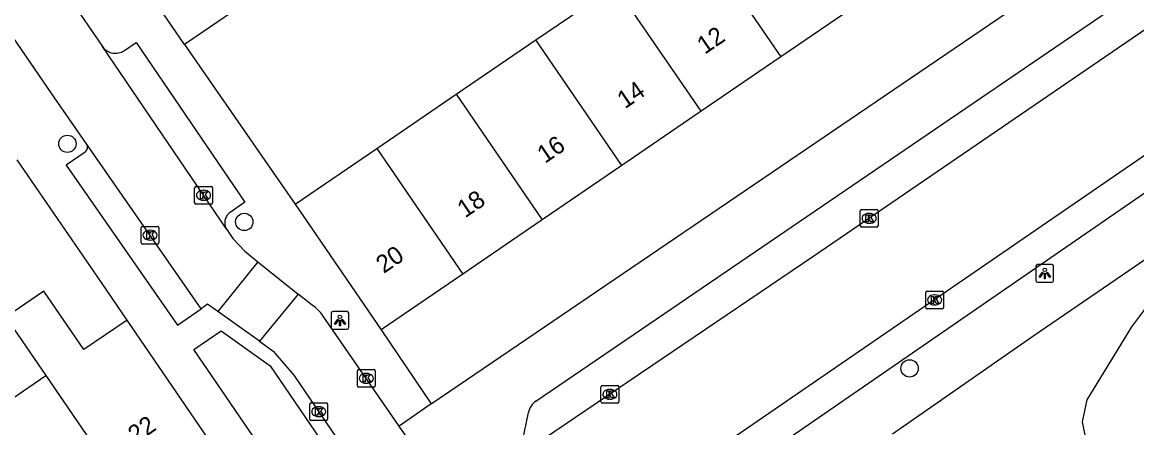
# Model space of a CAD drawing. Extents: x 157466 to 158888, y 383063 to 384677.
# Drawn here: x 158262.6 to 158325.5, y 383755.9 to 383778.8 of the extents above; entities that cross this region are included whole.
import ezdxf

# ---------------------------------------------------------------- set-up
doc = ezdxf.new("R2010")
doc.units = 0
for name, color, linetype in [('IMGEO_Boom', 7, 'Continuous'), ('IMGEO_Groenvoorziening', 7, 'Continuous'), ('IMGEO_Kolk', 7, 'Continuous'), ('IMGEO_Lichtpunt', 7, 'Continuous'), ('IMGEO_Muur', 7, 'Continuous'), ('IMGEO_Pand', 7, 'Continuous'), ('IMGEO_Pand_nummerreeks', 7, 'Continuous'), ('IMGEO_Rijbaan_lokaal_open', 7, 'Continuous'), ('IMGEO_Voetpad_open', 7, 'Continuous')]:
    doc.layers.add(name, color=color, linetype=linetype)

msp = doc.modelspace()

# ---------------------------------------------------------------- linework, layer by layer
at = {"layer": 'IMGEO_Boom'}
for centre in [(158265.189, 383771.9), (158275.165, 383767.49), (158312.693, 383759.216)]:
    msp.add_circle(centre, 0.489, dxfattribs=at)
at = {"layer": 'IMGEO_Groenvoorziening'}
msp.add_lwpolyline([(158334.12, 383750.607), (158332.791, 383751.81), (158334.867, 383754.492), (158334.342, 383755.707), (158335.525, 383757.421), (158335.831, 383758.461), (158335.729, 383760.44), (158335.26, 383762.521), (158334.199, 383764.378), (158332.852, 383765.317), (158331.363, 383765.643), (158329.241, 383765.255), (158327.956, 383764.603), (158326.446, 383763.215), (158325.206, 383761.562), (158322.692, 383757.441), (158322.427, 383756.197), (158322.692, 383754.891), (158323.059, 383754.054), (158339.545, 383730.388)], dxfattribs=at)
at = {"layer": 'IMGEO_Kolk'}
for p, q in [((158272.367, 383768.57), (158272.367, 383769.422)), ((158272.442, 383769.496), (158273.294, 383769.496)), ((158272.855, 383769.276), (158272.88, 383769.276)), ((158273.368, 383769.422), (158273.368, 383768.57)), ((158273.294, 383768.496), (158272.442, 383768.496)), ((158272.878, 383768.716), (158272.853, 383768.716)), ((158309.91, 383767.263), (158309.91, 383768.115)), ((158309.985, 383768.189), (158310.837, 383768.189)), ((158310.398, 383767.969), (158310.423, 383767.969)), ((158310.911, 383768.115), (158310.911, 383767.263)), ((158269.353, 383766.313), (158269.353, 383767.165)), ((158269.428, 383767.239), (158270.28, 383767.239)), ((158270.354, 383767.165), (158270.354, 383766.313)), ((158310.837, 383767.189), (158309.985, 383767.189)), ((158310.421, 383767.409), (158310.396, 383767.409)), ((158269.841, 383767.019), (158269.866, 383767.019)), ((158270.28, 383766.239), (158269.428, 383766.239)), ((158269.864, 383766.459), (158269.839, 383766.459)), ((158313.601, 383762.657), (158313.601, 383763.509)), ((158313.676, 383763.583), (158314.528, 383763.583)), ((158314.602, 383763.509), (158314.602, 383762.657)), ((158314.112, 383762.803), (158314.087, 383762.803)), ((158314.089, 383763.363), (158314.114, 383763.363)), ((158314.528, 383762.583), (158313.676, 383762.583)), ((158281.545, 383758.226), (158281.545, 383759.078)), ((158281.62, 383759.152), (158282.472, 383759.152)), ((158282.546, 383759.078), (158282.546, 383758.226)), ((158282.056, 383758.372), (158282.031, 383758.372)), ((158282.033, 383758.932), (158282.058, 383758.932)), ((158282.472, 383758.152), (158281.62, 383758.152)), ((158295.286, 383757.326), (158295.286, 383758.178)), ((158295.361, 383758.252), (158296.213, 383758.252)), ((158295.774, 383758.032), (158295.799, 383758.032)), ((158296.287, 383758.178), (158296.287, 383757.326)), ((158278.867, 383756.347), (158278.867, 383757.199)), ((158278.942, 383757.273), (158279.794, 383757.273)), ((158279.868, 383757.199), (158279.868, 383756.347)), ((158296.213, 383757.252), (158295.361, 383757.252)), ((158295.797, 383757.472), (158295.772, 383757.472)), ((158279.378, 383756.493), (158279.353, 383756.493)), ((158279.355, 383757.053), (158279.38, 383757.053)), ((158279.794, 383756.273), (158278.942, 383756.273))]:
    msp.add_line(p, q, dxfattribs=at)
for points in [[(158272.367, 383768.57), (158272.367, 383769.422)], [(158272.442, 383769.496), (158273.294, 383769.496)], [(158272.688, 383769.196), (158272.811, 383769.196), (158272.811, 383769.045), (158272.941, 383769.196), (158273.105, 383769.196), (158272.959, 383769.045), (158273.112, 383768.796), (158272.96, 383768.796), (158272.875, 383768.96), (158272.811, 383768.893), (158272.811, 383768.796), (158272.688, 383768.796), (158272.688, 383769.196)], [(158273.368, 383769.422), (158273.368, 383768.57)], [(158273.294, 383768.496), (158272.442, 383768.496)], [(158309.91, 383767.263), (158309.91, 383768.115)], [(158309.985, 383768.189), (158310.837, 383768.189)], [(158310.231, 383767.889), (158310.354, 383767.889), (158310.354, 383767.738), (158310.484, 383767.889), (158310.648, 383767.889), (158310.502, 383767.738), (158310.655, 383767.489), (158310.503, 383767.489), (158310.418, 383767.653), (158310.354, 383767.586), (158310.354, 383767.489), (158310.231, 383767.489), (158310.231, 383767.889)], [(158310.911, 383768.115), (158310.911, 383767.263)], [(158269.353, 383766.313), (158269.353, 383767.165)], [(158269.428, 383767.239), (158270.28, 383767.239)], [(158270.354, 383767.165), (158270.354, 383766.313)], [(158310.837, 383767.189), (158309.985, 383767.189)], [(158269.674, 383766.939), (158269.797, 383766.939), (158269.797, 383766.788), (158269.927, 383766.939), (158270.091, 383766.939), (158269.945, 383766.788), (158270.098, 383766.539), (158269.946, 383766.539), (158269.861, 383766.703), (158269.797, 383766.636), (158269.797, 383766.539), (158269.674, 383766.539), (158269.674, 383766.939)], [(158270.28, 383766.239), (158269.428, 383766.239)], [(158313.601, 383762.657), (158313.601, 383763.509)], [(158313.676, 383763.583), (158314.528, 383763.583)], [(158314.602, 383763.509), (158314.602, 383762.657)], [(158313.922, 383763.283), (158314.045, 383763.283), (158314.045, 383763.132), (158314.175, 383763.283), (158314.339, 383763.283), (158314.193, 383763.132), (158314.346, 383762.883), (158314.194, 383762.883), (158314.109, 383763.047), (158314.045, 383762.98), (158314.045, 383762.883), (158313.922, 383762.883), (158313.922, 383763.283)], [(158314.528, 383762.583), (158313.676, 383762.583)], [(158281.545, 383758.226), (158281.545, 383759.078)], [(158281.62, 383759.152), (158282.472, 383759.152)], [(158282.546, 383759.078), (158282.546, 383758.226)], [(158281.866, 383758.852), (158281.989, 383758.852), (158281.989, 383758.701), (158282.119, 383758.852), (158282.283, 383758.852), (158282.137, 383758.701), (158282.29, 383758.452), (158282.138, 383758.452), (158282.053, 383758.616), (158281.989, 383758.549), (158281.989, 383758.452), (158281.866, 383758.452), (158281.866, 383758.852)], [(158282.472, 383758.152), (158281.62, 383758.152)], [(158295.286, 383757.326), (158295.286, 383758.178)], [(158295.361, 383758.252), (158296.213, 383758.252)], [(158295.607, 383757.952), (158295.73, 383757.952), (158295.73, 383757.801), (158295.86, 383757.952), (158296.024, 383757.952), (158295.878, 383757.801), (158296.031, 383757.552), (158295.879, 383757.552), (158295.794, 383757.716), (158295.73, 383757.649), (158295.73, 383757.552), (158295.607, 383757.552), (158295.607, 383757.952)], [(158296.287, 383758.178), (158296.287, 383757.326)], [(158278.867, 383756.347), (158278.867, 383757.199)], [(158278.942, 383757.273), (158279.794, 383757.273)], [(158279.868, 383757.199), (158279.868, 383756.347)], [(158296.213, 383757.252), (158295.361, 383757.252)], [(158279.188, 383756.973), (158279.311, 383756.973), (158279.311, 383756.822), (158279.441, 383756.973), (158279.605, 383756.973), (158279.459, 383756.822), (158279.612, 383756.573), (158279.46, 383756.573), (158279.375, 383756.737), (158279.311, 383756.67), (158279.311, 383756.573), (158279.188, 383756.573), (158279.188, 383756.973)], [(158279.794, 383756.273), (158278.942, 383756.273)]]:
    msp.add_lwpolyline(points, dxfattribs=at)
for centre, start, end in [((158272.444, 383769.42), 91.55205, 178.44795), ((158272.444, 383769.42), 91.55205, 178.44795), ((158273.292, 383769.42), 1.55205, 88.44795), ((158273.292, 383769.42), 1.55205, 88.44795), ((158272.444, 383768.572), 181.55205, 268.44795), ((158272.444, 383768.572), 181.55205, 268.44795), ((158273.292, 383768.572), 271.55205, 358.44795), ((158273.292, 383768.572), 271.55205, 358.44795), ((158309.987, 383768.113), 91.55205, 178.44795), ((158309.987, 383768.113), 91.55205, 178.44795), ((158310.835, 383768.113), 1.55205, 88.44795), ((158310.835, 383768.113), 1.55205, 88.44795), ((158269.43, 383767.163), 91.55205, 178.44795), ((158269.43, 383767.163), 91.55205, 178.44795), ((158270.278, 383767.163), 1.55205, 88.44795), ((158270.278, 383767.163), 1.55205, 88.44795), ((158309.987, 383767.265), 181.55205, 268.44795), ((158309.987, 383767.265), 181.55205, 268.44795), ((158310.835, 383767.265), 271.55205, 358.44795), ((158310.835, 383767.265), 271.55205, 358.44795), ((158269.43, 383766.315), 181.55205, 268.44795), ((158269.43, 383766.315), 181.55205, 268.44795), ((158270.278, 383766.315), 271.55205, 358.44795), ((158270.278, 383766.315), 271.55205, 358.44795), ((158313.678, 383763.507), 91.55205, 178.44795), ((158313.678, 383763.507), 91.55205, 178.44795), ((158314.526, 383763.507), 1.55205, 88.44795), ((158314.526, 383763.507), 1.55205, 88.44795), ((158313.678, 383762.659), 181.55205, 268.44795), ((158313.678, 383762.659), 181.55205, 268.44795), ((158314.526, 383762.659), 271.55205, 358.44795), ((158314.526, 383762.659), 271.55205, 358.44795), ((158281.622, 383759.076), 91.55205, 178.44795), ((158281.622, 383759.076), 91.55205, 178.44795), ((158282.47, 383759.076), 1.55205, 88.44795), ((158282.47, 383759.076), 1.55205, 88.44795), ((158281.622, 383758.228), 181.55205, 268.44795), ((158281.622, 383758.228), 181.55205, 268.44795), ((158282.47, 383758.228), 271.55205, 358.44795), ((158282.47, 383758.228), 271.55205, 358.44795), ((158295.363, 383758.176), 91.55205, 178.44795), ((158295.363, 383758.176), 91.55205, 178.44795), ((158296.211, 383758.176), 1.55205, 88.44795), ((158296.211, 383758.176), 1.55205, 88.44795), ((158278.944, 383757.197), 91.55205, 178.44795), ((158278.944, 383757.197), 91.55205, 178.44795), ((158279.792, 383757.197), 1.55205, 88.44795), ((158279.792, 383757.197), 1.55205, 88.44795), ((158295.363, 383757.328), 181.55205, 268.44795), ((158295.363, 383757.328), 181.55205, 268.44795), ((158296.211, 383757.328), 271.55205, 358.44795), ((158296.211, 383757.328), 271.55205, 358.44795), ((158278.944, 383756.349), 181.55205, 268.44795), ((158278.944, 383756.349), 181.55205, 268.44795), ((158279.792, 383756.349), 271.55205, 358.44795), ((158279.792, 383756.349), 271.55205, 358.44795)]:
    msp.add_arc(centre, 0.0765, start, end, dxfattribs=at)
for centre, major_axis, ratio, start_param, end_param in [((158272.854, 383768.996), (-0.387, 0.002), 0.722429, 4.712389, 7.853982), ((158272.879, 383768.996), (-0.39, 0.002), 0.717154, 1.570796, 4.712389), ((158310.397, 383767.689), (-0.387, 0.002), 0.722429, 4.712389, 7.853982), ((158310.422, 383767.689), (-0.39, 0.002), 0.717154, 1.570796, 4.712389), ((158269.84, 383766.739), (-0.387, 0.002), 0.722429, 4.712389, 7.853982), ((158269.865, 383766.739), (-0.39, 0.002), 0.717154, 1.570796, 4.712389), ((158314.088, 383763.083), (-0.387, 0.002), 0.722429, 4.712389, 7.853982), ((158314.113, 383763.083), (-0.39, 0.002), 0.717154, 1.570796, 4.712389), ((158282.032, 383758.652), (-0.387, 0.002), 0.722429, 4.712389, 7.853982), ((158282.057, 383758.652), (-0.39, 0.002), 0.717154, 1.570796, 4.712389), ((158295.773, 383757.752), (-0.387, 0.002), 0.722429, 4.712389, 7.853982), ((158295.798, 383757.752), (-0.39, 0.002), 0.717154, 1.570796, 4.712389), ((158279.354, 383756.773), (-0.387, 0.002), 0.722429, 4.712389, 7.853982), ((158279.379, 383756.773), (-0.39, 0.002), 0.717154, 1.570796, 4.712389)]:
    msp.add_ellipse(centre, major_axis=major_axis, ratio=ratio, start_param=start_param, end_param=end_param, dxfattribs=at)
at = {"layer": 'IMGEO_Lichtpunt'}
for p, q in [((158319.821, 383764.981), (158319.821, 383764.174)), ((158319.821, 383764.981), (158319.821, 383764.174)), ((158320.723, 383765.076), (158319.915, 383765.076)), ((158320.723, 383765.076), (158319.915, 383765.076)), ((158320.817, 383764.174), (158320.817, 383764.981)), ((158320.817, 383764.174), (158320.817, 383764.981)), ((158319.915, 383764.08), (158320.723, 383764.08)), ((158319.915, 383764.08), (158320.723, 383764.08)), ((158280.061, 383762.329), (158280.061, 383761.522)), ((158280.061, 383762.329), (158280.061, 383761.522)), ((158280.963, 383762.424), (158280.155, 383762.424)), ((158280.963, 383762.424), (158280.155, 383762.424)), ((158281.057, 383761.522), (158281.057, 383762.329)), ((158281.057, 383761.522), (158281.057, 383762.329)), ((158280.155, 383761.428), (158280.963, 383761.428)), ((158280.155, 383761.428), (158280.963, 383761.428))]:
    msp.add_line(p, q, dxfattribs=at)
for points in [[(158320.195, 383764.645), (158320.234, 383764.617), (158320.046, 383764.355), (158320.008, 383764.382), (158320.195, 383764.645)], [(158320.297, 383764.597), (158320.344, 383764.597), (158320.344, 383764.275), (158320.297, 383764.275), (158320.297, 383764.597)], [(158320.407, 383764.617), (158320.445, 383764.644), (158320.632, 383764.382), (158320.593, 383764.354), (158320.407, 383764.617)], [(158280.435, 383761.993), (158280.474, 383761.965), (158280.286, 383761.703), (158280.248, 383761.73), (158280.435, 383761.993)], [(158280.537, 383761.945), (158280.584, 383761.945), (158280.584, 383761.623), (158280.537, 383761.623), (158280.537, 383761.945)], [(158280.647, 383761.965), (158280.685, 383761.992), (158280.872, 383761.73), (158280.833, 383761.702), (158280.647, 383761.965)]]:
    msp.add_lwpolyline(points, dxfattribs=at)
for centre in [(158320.32, 383764.779), (158280.56, 383762.127)]:
    msp.add_circle(centre, 0.0994, dxfattribs=at)
for centre, start, end in [((158319.915, 383764.981), 90, 180), ((158319.915, 383764.981), 90, 180), ((158320.723, 383764.981), 0, 90), ((158320.723, 383764.981), 0, 90), ((158319.915, 383764.174), 180, 270), ((158319.915, 383764.174), 180, 270), ((158320.723, 383764.174), 270, 0), ((158320.723, 383764.174), 270, 360), ((158280.155, 383762.329), 90, 180), ((158280.155, 383762.329), 90, 180), ((158280.963, 383762.329), 0, 90), ((158280.963, 383762.329), 0, 90), ((158280.155, 383761.522), 180, 270), ((158280.155, 383761.522), 180, 270), ((158280.963, 383761.522), 270, 0), ((158280.963, 383761.522), 270, 360)]:
    msp.add_arc(centre, 0.0946, start, end, dxfattribs=at)
at = {"layer": 'IMGEO_Muur'}
for points in [[(158276.328, 383770.951), (158278.034, 383768.483)], [(158268.557, 383761.942), (158266.902, 383764.36)]]:
    msp.add_lwpolyline(points, dxfattribs=at)
at = {"layer": 'IMGEO_Pand'}
for points in [[(158300.579, 383783.896), (158305.428, 383776.804)], [(158270.2, 383779.842), (158273.433, 383782.053), (158275.031, 383779.716), (158271.798, 383777.505)], [(158291.609, 383777.764), (158296.094, 383780.83)], [(158300.943, 383773.738), (158296.094, 383780.83)], [(158271.798, 383777.505), (158270.2, 383779.842)], [(158309.912, 383779.87), (158305.428, 383776.804)], [(158287.124, 383774.698), (158291.609, 383777.764)], [(158296.458, 383770.672), (158291.609, 383777.764)], [(158305.428, 383776.804), (158300.943, 383773.738)], [(158282.64, 383771.632), (158287.124, 383774.698)], [(158287.124, 383774.698), (158291.973, 383767.606)], [(158300.943, 383773.738), (158296.458, 383770.672)], [(158278.034, 383768.483), (158282.64, 383771.632)], [(158282.64, 383771.632), (158287.488, 383764.539)], [(158296.458, 383770.672), (158291.973, 383767.606)], [(158278.034, 383768.483), (158282.883, 383761.391)], [(158291.973, 383767.606), (158287.488, 383764.539)], [(158287.488, 383764.539), (158282.883, 383761.391)], [(158268.557, 383761.942), (158266.124, 383760.28), (158263.866, 383763.582), (158261.72, 383762.115), (158263.977, 383758.813)], [(158273.392, 383754.863), (158268.557, 383761.942)], [(158259.524, 383755.771), (158263.977, 383758.813)], [(158263.977, 383758.813), (158268.814, 383751.734)]]:
    msp.add_lwpolyline(points, dxfattribs=at)
at = {"layer": 'IMGEO_Rijbaan_lokaal_open'}
for points in [[(158330.351, 383781.361), (158307.283, 383765.552), (158290.185, 383753.958)], [(158265.297, 383780.146), (158265.304, 383780.135), (158267.164, 383777.394)], [(158266.276, 383771.893), (158264.308, 383774.728), (158262.112, 383777.939)], [(158274.182, 383767.055), (158267.164, 383777.394)], [(158282.459, 383741.394), (158290.097, 383746.61), (158295.037, 383750), (158330.85, 383774.628), (158335.089, 383777.517)], [(158272.742, 383762.581), (158266.276, 383771.893)], [(158274.182, 383767.055), (158274.521, 383766.556), (158275.19, 383765.845), (158275.936, 383765.242)], [(158275.936, 383765.242), (158273.675, 383762.423)], [(158275.936, 383765.242), (158278.203, 383763.409)], [(158278.203, 383763.409), (158276.019, 383760.753)], [(158283.897, 383755.957), (158279.624, 383762.174), (158279.49, 383762.35), (158279.341, 383762.513), (158279.178, 383762.661), (158279.002, 383762.795), (158278.82, 383762.91), (158278.203, 383763.409)], [(158273.675, 383762.423), (158273.097, 383762.835), (158272.742, 383762.581)], [(158276.019, 383760.753), (158273.675, 383762.423)], [(158276.019, 383760.753), (158276.8, 383760.196), (158277.966, 383758.835), (158280.976, 383754.417), (158281.209, 383754.075)], [(158284.664, 383754.841), (158283.897, 383755.957)]]:
    msp.add_lwpolyline(points, dxfattribs=at)
at = {"layer": 'IMGEO_Voetpad_open'}
for points in [[(158285.703, 383757.214), (158328.509, 383786.356), (158330.843, 383787.992)], [(158291.616, 383757.372), (158326.484, 383781.177)], [(158267.164, 383777.394), (158267.213, 383777.331), (158267.267, 383777.272), (158267.327, 383777.218), (158267.391, 383777.17), (158267.459, 383777.128), (158267.53, 383777.091), (158267.604, 383777.062), (158267.681, 383777.039), (158267.76, 383777.023), (158267.839, 383777.015), (158267.919, 383777.013), (158267.999, 383777.019), (158268.078, 383777.031), (158268.156, 383777.051), (158268.232, 383777.078), (158268.304, 383777.111), (158268.374, 383777.15), (158268.404, 383777.17), (158269.076, 383777.628), (158275.206, 383768.597), (158274.368, 383768.025), (158274.318, 383767.988), (158274.271, 383767.947), (158274.229, 383767.901), (158274.19, 383767.853), (158274.157, 383767.8), (158274.127, 383767.745), (158274.103, 383767.688), (158274.084, 383767.629), (158274.071, 383767.568), (158274.063, 383767.506), (158274.061, 383767.444), (158274.064, 383767.382), (158274.072, 383767.321), (158274.086, 383767.26), (158274.106, 383767.201), (158274.13, 383767.144), (158274.16, 383767.089), (158274.182, 383767.055)], [(158271.798, 383777.505), (158276.328, 383770.951), (158278.034, 383768.483)], [(158311.73, 383755.524), (158319.648, 383761.029), (158331.55, 383769.183), (158341.786, 383776.163), (158343.635, 383773.521), (158344.682, 383774.246)], [(158331.24, 383772.758), (158299.245, 383750.676)], [(158268.557, 383761.942), (158266.902, 383764.36), (158262.353, 383771.002)], [(158266.189, 383771.436), (158265.115, 383770.703), (158271.393, 383761.66), (158272.742, 383762.581)], [(158276.62, 383759.361), (158280.256, 383754.037), (158277.76, 383752.323), (158272.324, 383760.284), (158273.854, 383761.334), (158276.62, 383759.361)], [(158282.883, 383761.391), (158285.703, 383757.214)], [(158285.703, 383757.214), (158283.897, 383755.957)], [(158290.854, 383755.086), (158291.193, 383756.731)]]:
    msp.add_lwpolyline(points, dxfattribs=at)
for centre, radius, start, end in [((158265.97, 383771.714), 0.354, 308.17377, 30.26916), ((158292.284, 383756.471), 1.121, 126.54904, 166.60881)]:
    msp.add_arc(centre, radius, start, end, dxfattribs=at)

# ---------------------------------------------------------------- texts
at = {"layer": 'IMGEO_Pand_nummerreeks'}
for s, rotation, p in [('12', 34.35943, (158301.144, 383776.929)), ('14', 34.35943, (158296.637, 383773.848)), ('16', 34.35943, (158292.127, 383770.765)), ('18', 34.35943, (158287.621, 383767.683)), ('20', 34.35943, (158283.036, 383764.549)), ('22', 34.35124, (158269.047, 383754.946))]:
    msp.add_text(s, height=1, rotation=rotation, dxfattribs=at).set_placement(p)

doc.saveas('drawing.dxf')
